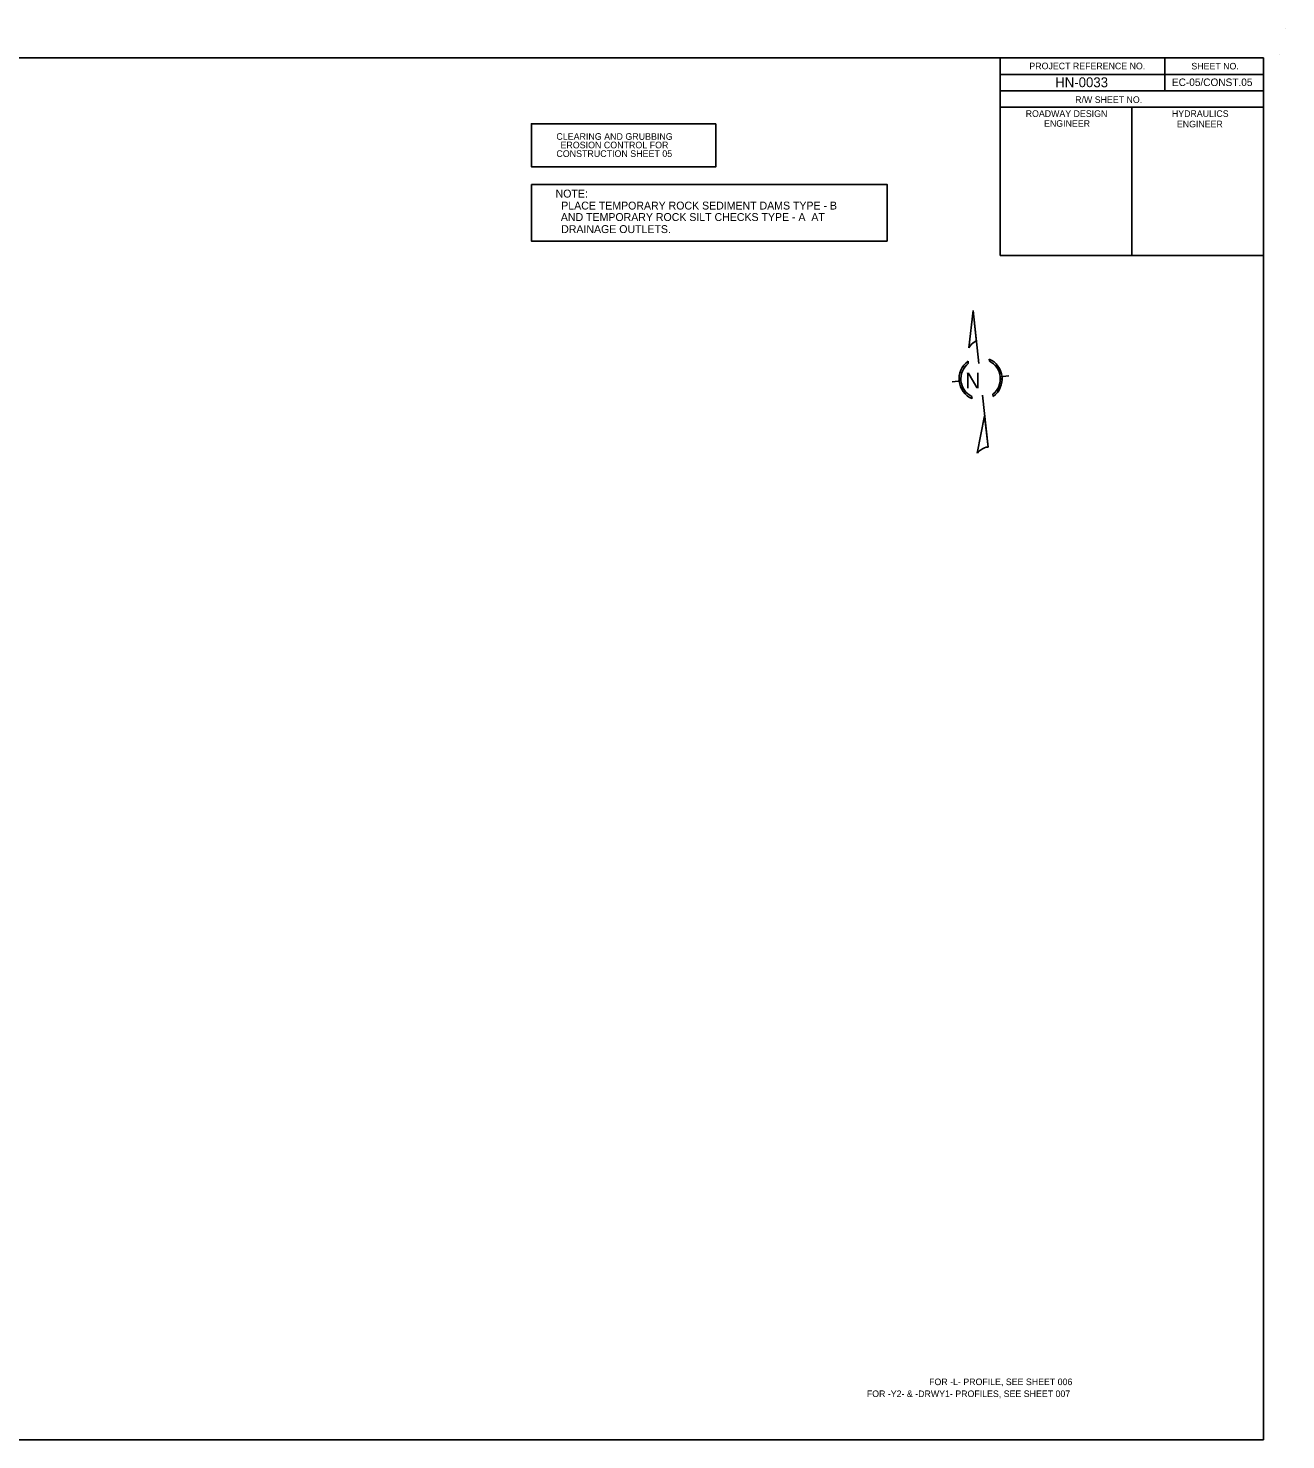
# Model space of a CAD drawing. Extents: x -0.38 to 2.81, y 0 to 1.82.
# Drawn here: x 1.213 to 2.806, y 0.037 to 1.825 of the extents above; entities that cross this region are included whole.
import ezdxf

# ---------------------------------------------------------------- set-up
doc = ezdxf.new("R2010")
doc.units = 0
for name, color, linetype in [('Blank Plan Sheet Both CELL', 7, 'Continuous'), ('Construction Sheet Number Note CG CELL', 7, 'Continuous'), ('P_RDY_North Arrow_for_Plan_Sheets_Cell', 7, 'Continuous'), ('Sediment Dams and Silt Check Note CG CELL', 7, 'Continuous'), ('Sheet_Plan_CELL', 7, 'Continuous')]:
    doc.layers.add(name, color=color, linetype=linetype)

msp = doc.modelspace()

# ---------------------------------------------------------------- linework, layer by layer
at = {"layer": 'Blank Plan Sheet Both CELL'}
for p, q in [((2.8058, 1.825), (2.8058, 1.825)), ((2.7983, 1.7917), (2.7983, 1.7917)), ((2.6525, 1.7874), (2.6525, 1.7457)), ((2.4441, 1.7666), (2.7775, 1.7666)), ((2.4441, 1.7457), (2.7775, 1.7457)), ((2.4441, 1.7457), (2.4441, 1.7249)), ((2.4441, 1.7457), (2.7775, 1.7457)), ((2.6108, 1.7249), (2.6108, 1.5375))]:
    msp.add_line(p, q, dxfattribs=at)
for points in [[(2.7775, 1.7875), (0.2775, 1.7875), (0.2775, 0.0375), (2.7775, 0.0375)], [(2.4441, 1.7875), (2.7775, 1.7875), (2.7775, 1.7457), (2.4441, 1.7457)], [(2.4441, 1.7249), (2.6108, 1.7249), (2.6108, 1.5374), (2.4441, 1.5374)], [(2.6108, 1.7249), (2.7775, 1.7249), (2.7775, 1.5374), (2.6108, 1.5374)]]:
    msp.add_lwpolyline(points, close=True, dxfattribs=at)
at = {"layer": 'Construction Sheet Number Note CG CELL'}
msp.add_lwpolyline([(2.084, 1.7041), (1.8504, 1.7041), (1.8504, 1.6495), (2.084, 1.6495)], close=True, dxfattribs=at)
at = {"layer": 'P_RDY_North Arrow_for_Plan_Sheets_Cell'}
for p, q in [((2.4044, 1.4204), (2.4099, 1.4676)), ((2.4172, 1.4004), (2.4099, 1.4676)), ((2.4099, 1.4676), (2.4099, 1.4676)), ((2.4099, 1.4676), (2.4099, 1.4676)), ((2.4099, 1.4676), (2.4143, 1.4272)), ((2.4143, 1.4272), (2.4142, 1.4284)), ((2.4142, 1.4284), (2.4142, 1.4284)), ((2.4034, 1.4032), (2.4037, 1.4005)), ((2.4034, 1.4032), (2.4034, 1.4032)), ((2.4305, 1.4034), (2.4302, 1.4061)), ((2.3835, 1.3771), (2.3945, 1.3783)), ((2.3945, 1.3783), (2.3922, 1.378)), ((2.3922, 1.378), (2.3945, 1.3783)), ((2.4442, 1.3837), (2.4551, 1.3849)), ((2.4442, 1.3837), (2.4465, 1.3839)), ((2.4465, 1.3839), (2.4442, 1.3837)), ((2.4083, 1.3586), (2.4086, 1.3559)), ((2.4288, 1.2944), (2.4216, 1.3605)), ((2.4353, 1.3588), (2.435, 1.3615)), ((2.4353, 1.3588), (2.4353, 1.3588)), ((2.4244, 1.3341), (2.4151, 1.2869)), ((2.4288, 1.2944), (2.4244, 1.3341))]:
    msp.add_line(p, q, dxfattribs=at)
for radius, start, end in [(0.0273, 125.6369, 246.7686), (0.025, 128.7059, 243.6996), (0.0273, 305.7231, 66.6823), (0.0273, 6.2027, 66.6823), (0.025, 308.8033, 63.6022), (0.025, 6.2027, 63.6022), (0.0273, 186.2027, 246.7686), (0.025, 186.2027, 243.6996)]:
    msp.add_arc((2.4193, 1.381), radius, start, end, dxfattribs=at)
for centre, major_axis, ratio, start_param, end_param in [((2.4093, 1.4238), (0.00485, 0.00463), 0.261723, 6.225794, 8.917625), ((2.4193, 1.381), (-0.003, 0.0272), 0.998737, 0.514018, 1.570796), ((2.4193, 1.381), (-0.0027, 0.0249), 0.998737, 0.567287, 1.570796), ((2.4193, 1.381), (-0.0027, 0.0249), 0.998737, 3.71058, 4.712389), ((2.4193, 1.381), (-0.003, 0.0272), 0.998737, 3.657116, 4.712389), ((2.422, 1.2904), (0.00679, 0.00399), 0.225493, 6.280036, 9.220301)]:
    msp.add_ellipse(centre, major_axis=major_axis, ratio=ratio, start_param=start_param, end_param=end_param, dxfattribs=at)
at = {"layer": 'Sediment Dams and Silt Check Note CG CELL'}
msp.add_lwpolyline([(1.8503, 1.6273), (1.8503, 1.5555), (2.3009, 1.5555), (2.3009, 1.6273)], close=True, dxfattribs=at)

# ---------------------------------------------------------------- texts
at = {"layer": 'Blank Plan Sheet Both CELL'}
for s, height, p in [('PROJECT REFERENCE NO.', 0.008333, (2.4811, 1.773)), ('SHEET NO.', 0.00833, (2.6863, 1.7728)), ('HN-0033', 0.0125, (2.5138, 1.7503)), (' EC-05/CONST.05 ', 0.009529, (2.6581, 1.7518)), ('R/W SHEET NO.', 0.008333, (2.5391, 1.7304)), ('ROADWAY DESIGN', 0.008333, (2.4764, 1.7127)), ('HYDRAULICS', 0.00833, (2.6616, 1.7127)), ('ENGINEER', 0.00833, (2.4997, 1.7002)), ('ENGINEER', 0.00833, (2.6679, 1.6995))]:
    msp.add_text(s, height=height, rotation=360, dxfattribs=at).set_placement(p)
at = {"layer": 'Construction Sheet Number Note CG CELL'}
for s, p in [('CLEARING AND GRUBBING', (1.882, 1.6837)), ('EROSION CONTROL FOR', (1.8872, 1.6729)), ('CONSTRUCTION SHEET 05', (1.882, 1.662))]:
    msp.add_text(s, height=0.0084, dxfattribs=at).set_placement(p)
at = {"layer": 'P_RDY_North Arrow_for_Plan_Sheets_Cell'}
msp.add_text('N', height=0.02, rotation=0.3801, dxfattribs=at).set_placement((2.3998, 1.3688))
at = {"layer": 'Sediment Dams and Silt Check Note CG CELL'}
for s, p in [('NOTE:', (1.881, 1.6106)), ('     AND TEMPORARY ROCK SILT CHECKS TYPE - A  AT', (1.8691, 1.5809)), ('     PLACE TEMPORARY ROCK SEDIMENT DAMS TYPE - B', (1.8696, 1.5954)), ('     DRAINAGE OUTLETS.', (1.8695, 1.5656))]:
    msp.add_text(s, height=0.01, dxfattribs=at).set_placement(p)
at = {"layer": 'Sheet_Plan_CELL'}
for s, p in [('FOR -L- PROFILE, SEE SHEET 006', (2.3541, 0.1067)), ('FOR -Y2- & -DRWY1- PROFILES, SEE SHEET 007', (2.2752, 0.0916))]:
    msp.add_text(s, height=0.008333, dxfattribs=at).set_placement(p)

doc.saveas('drawing.dxf')
